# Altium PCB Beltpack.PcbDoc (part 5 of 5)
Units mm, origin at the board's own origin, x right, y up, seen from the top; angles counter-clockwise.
Board outline 85 x 81 mm, 4 copper layers (Top Layer, Inner-1, Inner_GND, Bottom Layer), stack 1.556 mm thick; 389 components, 291 nets, 1372 pads, 660 vias.
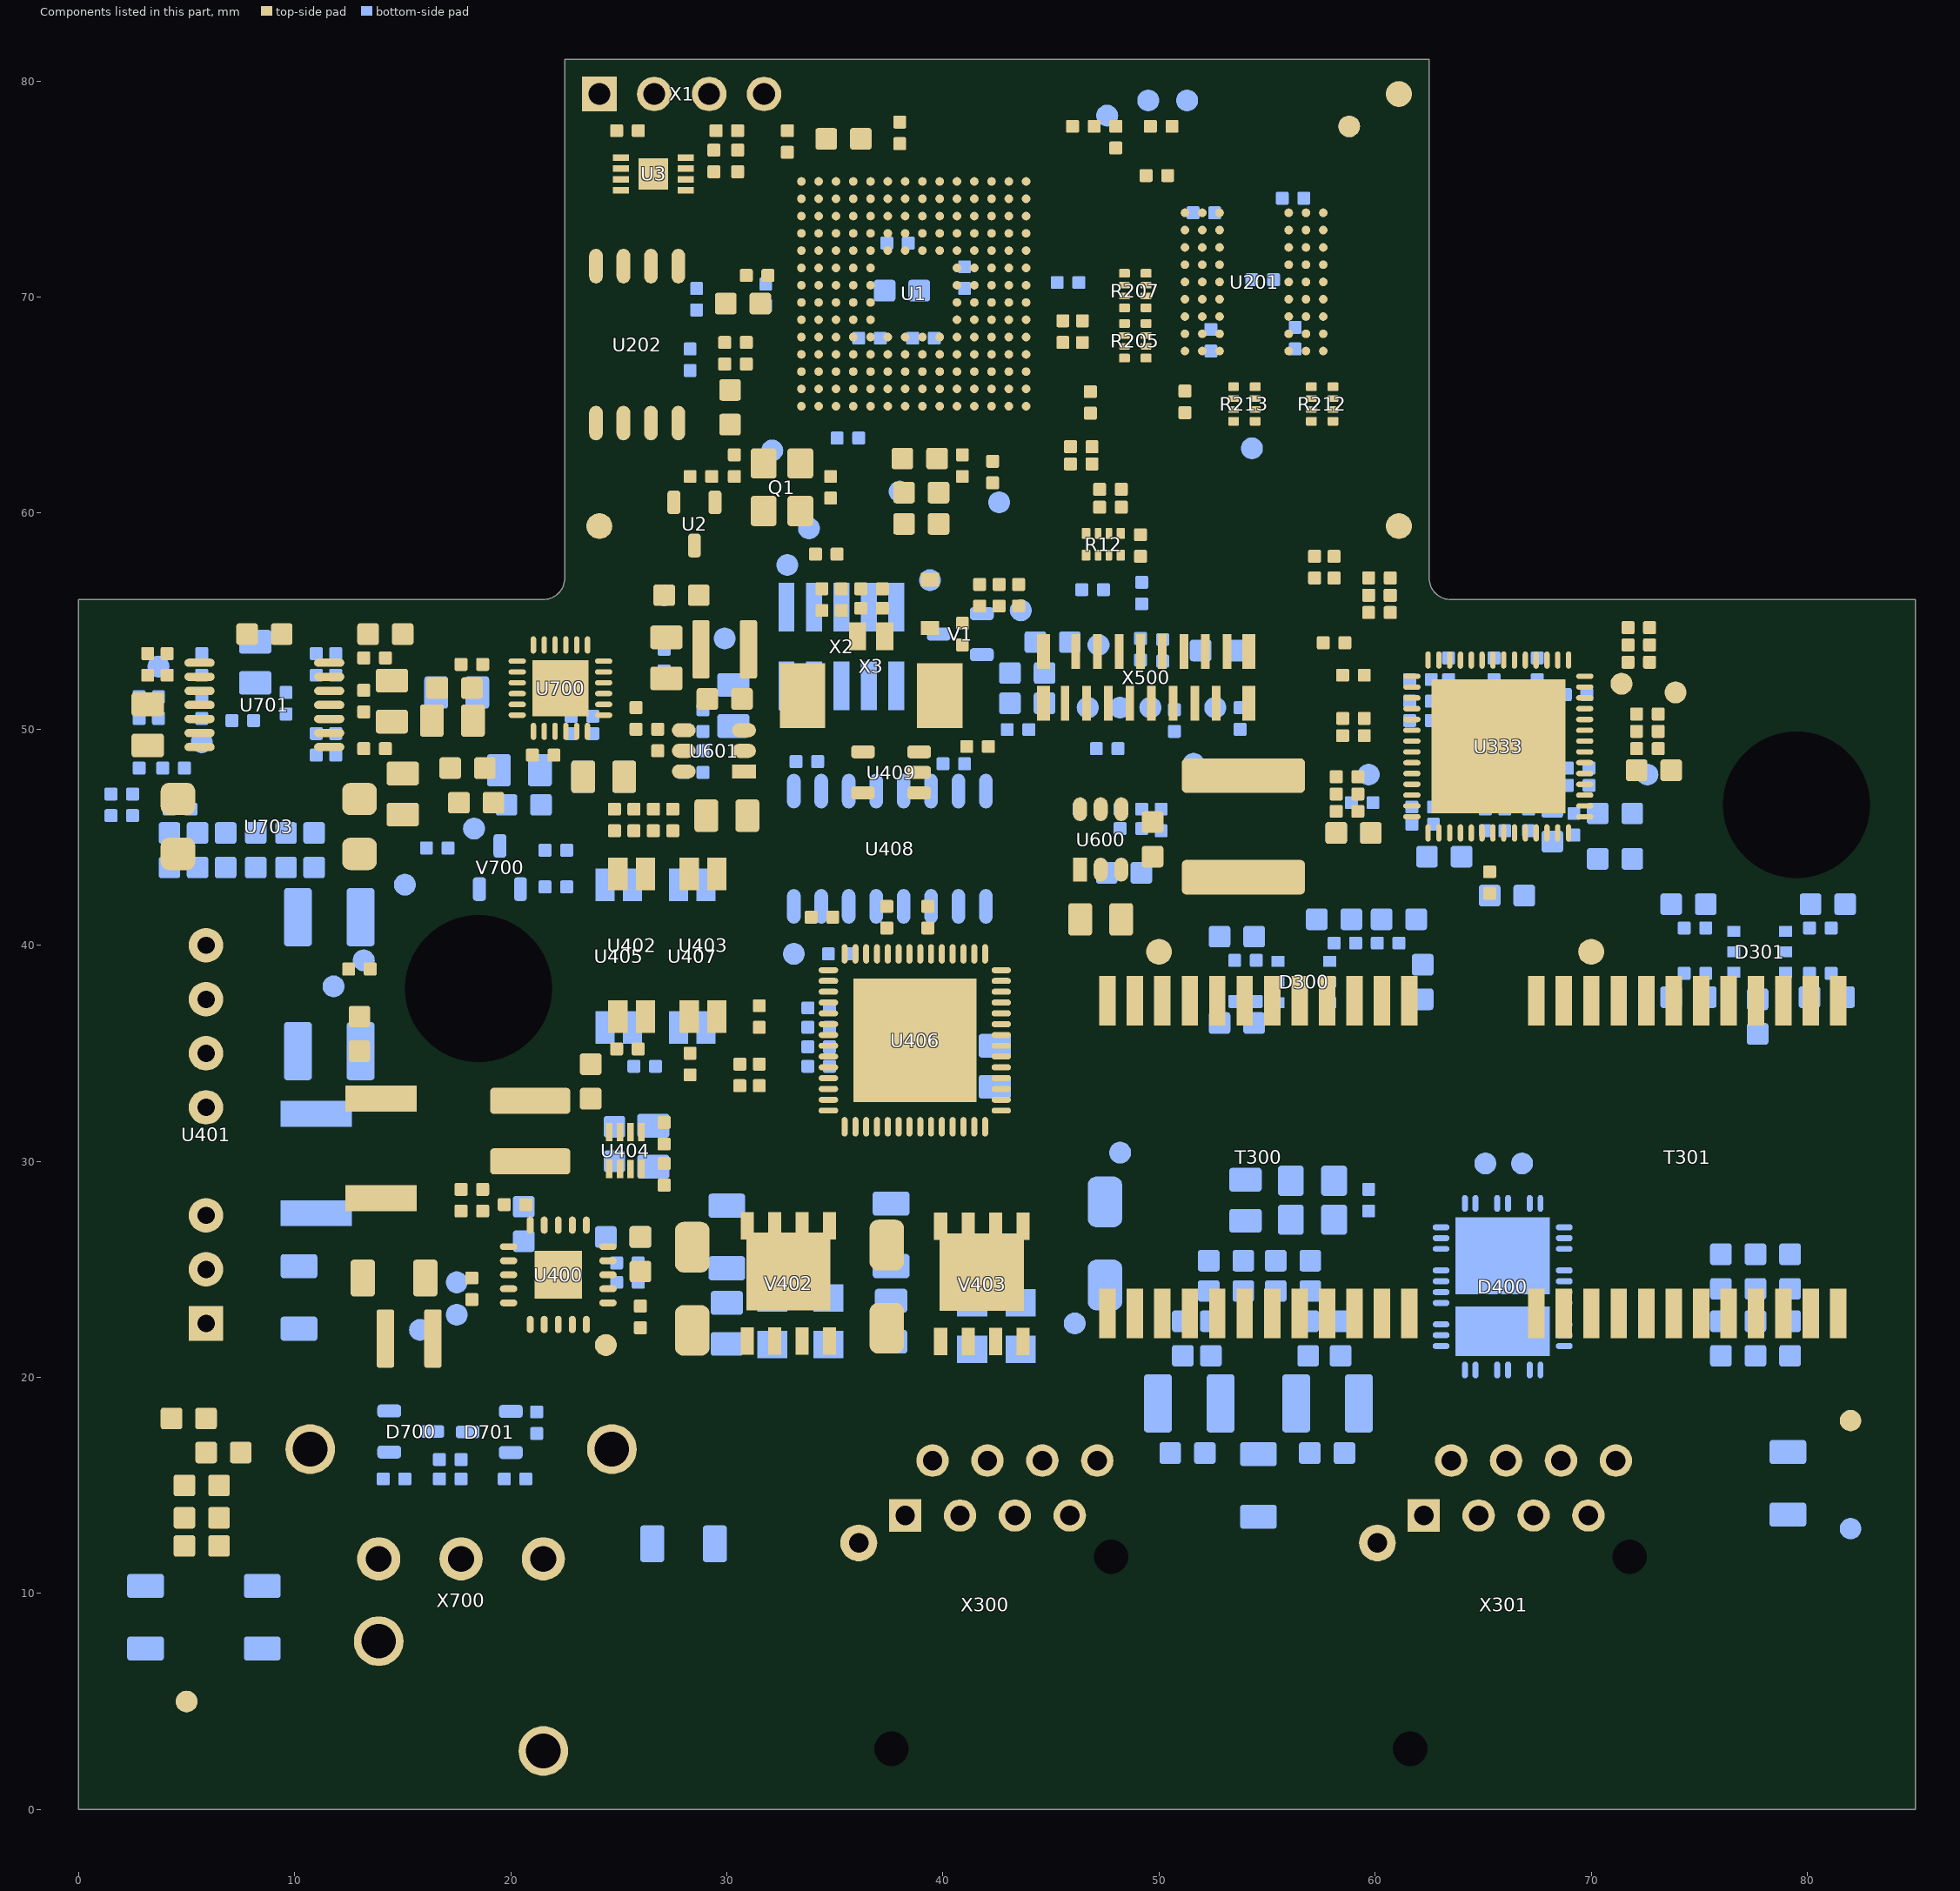
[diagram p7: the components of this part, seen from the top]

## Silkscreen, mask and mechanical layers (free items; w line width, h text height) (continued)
Title Block:
  lines w0.127: -35.983,-11.754 -30.903,-11.754 ; -35.983,36.506 -30.903,36.506 ; -35.983,84.766 -30.903,84.766 ; 37.042,-60.014 37.042,-54.934 ; 37.042,127.946 37.042,133.026 ; 101.177,-54.934 136.737,-54.934 ; 110.067,-60.014 110.067,-54.934 ; 110.067,127.946 110.067,133.026 ; 136.737,-49.854 250.91,-49.854 ; 174.837,-54.934 174.837,-44.901 ; 183.092,-60.014 183.092,-54.934 ; 183.092,127.946 183.092,133.026 ; 210.143,-44.774 210.143,-33.09 ; 228.177,-54.934 228.177,-44.774 ; 251.037,-44.774 136.737,-44.774 ; 251.037,-11.754 256.117,-11.754 ; 251.037,36.506 256.117,36.506 ; 251.037,84.766 256.117,84.766 ; 136.737,-54.934 251.037,-54.934 ; 136.737,-54.934 136.737,-44.774 ; 136.737,-44.774 136.737,-33.09 251.037,-33.09 251.037,-54.934 ; 251.037,-54.934 -30.903,-54.934 -30.903,127.946 251.037,127.946 251.037,-54.934 ; -35.983,-60.014 -35.983,133.026 256.117,133.026 256.117,-60.014 -35.983,-60.014
  text "1" at 0.263,129.597 h1.78
  text "2" at 72.907,129.597 h1.78
  text "3" at 146.059,129.597 h1.78
  text "4" at 218.957,129.597 h1.78
  text "A" at -34.078,106.585 h1.78
  text "A" at 252.942,106.585 h1.78
  text "B" at -34.078,58.528 h1.78
  text "B" at 252.942,58.528 h1.78
  text "C" at -34.078,10.014 h1.78
  text "C" at 252.942,10.014 h1.78
  text "TITLE:" at 138.642,-37.916 h1.14
  text "D" at -34.078,-37.992 h1.78
  text "D" at 252.942,-37.992 h1.78
  text ".PRJ_TITLE" at 146.9,-38.6 h5.08
  text "PUNQTUM" at 212.5,-41 h7
  text "DPL Beltpack" at 147.1,-41.8 h3
  text "ENGINEER:" at 138.642,-47.949 h1.14
  text "PART NO.:" at 176.107,-48.076 h1.14
  text "B.DPLBP_MAIN" at 188.553,-48.076 h2.54
  text "REV:" at 229.447,-48.203 h1.14
  text "Silvio Gehri" at 152.866,-48.33 h2.54
  text ".PRJ_Revision" at 235.67,-48.33 h2.54
  text "FILE NAME:" at 175.98,-53.029 h1.14
  text "PCB DESIGNER:" at 138.642,-53.156 h1.14
  text "Silvio Gehri" at 152.612,-53.156 h2.54
  text "DATE:" at 229.447,-53.156 h1.14
  text ".PCB_FILE_NAME_NO_PATH" at 188.426,-53.283 h2.54
  text ".PRINT_DATE" at 235.67,-53.283 h2.54
  text "1" at 0.263,-58.363 h1.78
  text "2" at 72.907,-58.363 h1.78
  text "3" at 146.059,-58.363 h1.78
  text "4" at 218.957,-58.363 h1.78

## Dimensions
62,59.4 to 61.1,79.4 on Dimensions
61.1,79.4 to 24.1,79.4 on Dimensions
21.5,57 to 21.7,55.4 on Dimensions
63.5,57 to 64.2,59.5 on Dimensions
85,0 to 0,0 on Dimensions
79.5,46.5 to 85,0 on Dimensions
18.5,38 to 0,0 on Dimensions
0,56 to 0,0 on Dimensions
85,56 to 79.5,46.5 on Dimensions
22.5,57 to 0,56 on Dimensions
21.5,56 to 22.5,81 on Dimensions
62.5,81 to 22.5,81 on Dimensions
18.5,38 to 0,56 on Dimensions
85,56 to 62.5,81 on Dimensions
22.5,81 to 0,0 on Dimensions
0,0 to 17.7,11.6 on Dimensions
17.7,11.6 to 42.7,-1 on Dimensions
42.7,-1 to 66.7,-1 on Dimensions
